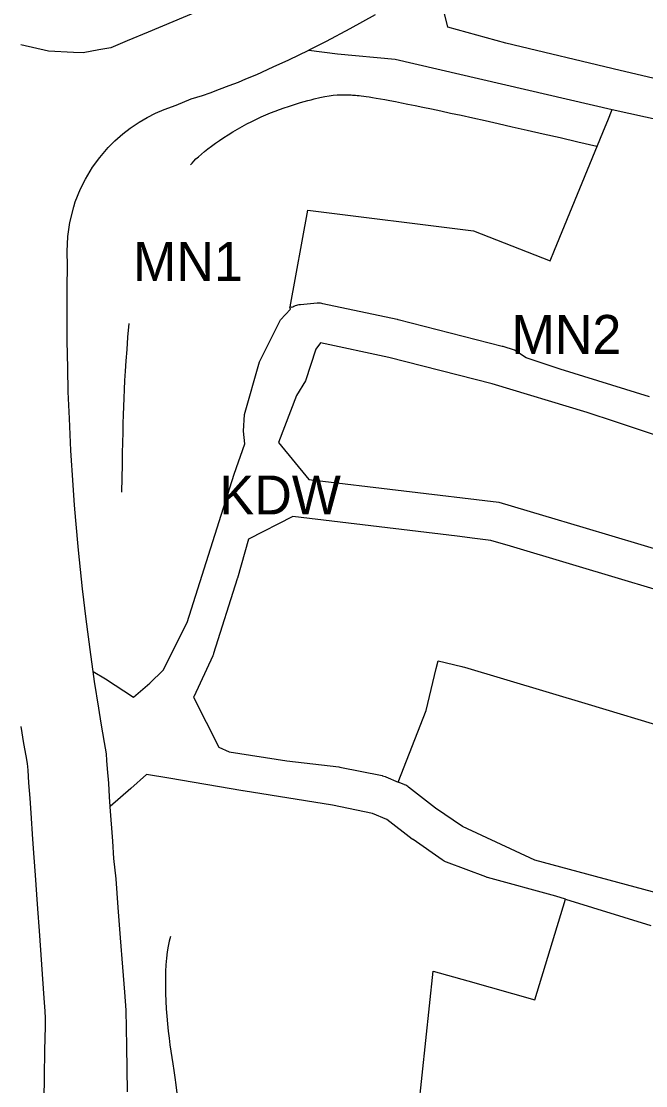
# Model space of a CAD drawing. Extents: x 7413438 to 7416393, y 5541665 to 5544118.
# Drawn here: x 7414642.6 to 7414738.9, y 5542699.5 to 5542863.7 of the extents above; entities that cross this region are included whole.
import ezdxf

# ---------------------------------------------------------------- set-up
doc = ezdxf.new("R2010")
doc.units = 0
for name, color, linetype in [('linie_rozgraniczajace', 7, 'Continuous'), ('linie_zabudowy_nieprzekraczalne', 7, 'Continuous'), ('oznaczenia_przeznaczen', 7, 'Continuous')]:
    doc.layers.add(name, color=color, linetype=linetype)

msp = doc.modelspace()

# ---------------------------------------------------------------- linework, layer by layer
at = {"layer": 'linie_rozgraniczajace'}
for p, q in [((7414708.4, 5542862.85), (7414706.47, 5542870.48)), ((7414669.79, 5542865.24), (7414662.17, 5542862.07)), ((7414697.17, 5542864.75), (7414693.28, 5542862.58)), ((7414662.17, 5542862.07), (7414658.93, 5542860.71)), ((7414693.28, 5542862.58), (7414689.64, 5542860.65)), ((7414717.31, 5542860.37), (7414708.4, 5542862.85)), ((7414646.79, 5542859.15), (7414642.54, 5542860.1)), ((7414658.93, 5542860.71), (7414656.43, 5542859.65)), ((7414689.64, 5542860.65), (7414686.96, 5542859.3)), ((7414734.97, 5542856.15), (7414717.31, 5542860.37)), ((7414650.67, 5542858.95), (7414646.79, 5542859.15)), ((7414652.15, 5542858.88), (7414650.67, 5542858.95)), ((7414654.58, 5542859.32), (7414652.15, 5542858.88)), ((7414656.43, 5542859.65), (7414654.58, 5542859.32)), ((7414683.85, 5542857.8), (7414686.96, 5542859.3)), ((7414686.96, 5542859.3), (7414691.38, 5542858.73)), ((7414691.38, 5542858.73), (7414700.27, 5542857.89)), ((7414681.46, 5542856.7), (7414683.85, 5542857.8)), ((7414700.27, 5542857.89), (7414733.74, 5542850.13)), ((7414677.26, 5542854.85), (7414678.93, 5542855.55)), ((7414678.93, 5542855.55), (7414681.46, 5542856.7)), ((7414746.66, 5542853.39), (7414734.97, 5542856.15)), ((7414673.19, 5542853.28), (7414674.64, 5542853.82)), ((7414674.64, 5542853.82), (7414676.09, 5542854.36)), ((7414676.09, 5542854.36), (7414677.26, 5542854.85)), ((7414668.8, 5542851.76), (7414670.53, 5542852.3)), ((7414670.53, 5542852.3), (7414671.71, 5542852.73)), ((7414671.71, 5542852.73), (7414673.19, 5542853.28)), ((7414664.65, 5542850.11), (7414666.47, 5542850.79)), ((7414666.47, 5542850.79), (7414668.8, 5542851.76)), ((7414660.81, 5542848.2), (7414662.04, 5542848.91)), ((7414662.04, 5542848.91), (7414663.33, 5542849.56)), ((7414663.33, 5542849.56), (7414664.65, 5542850.11)), ((7414733.06, 5542848.45), (7414733.74, 5542850.13)), ((7414733.74, 5542850.13), (7414741.44, 5542848.45)), ((7414658.26, 5542846.38), (7414659.42, 5542847.27)), ((7414659.42, 5542847.27), (7414660.81, 5542848.2)), ((7414724.84, 5542828.41), (7414732.64, 5542847.44)), ((7414732.64, 5542847.44), (7414732.65, 5542847.44)), ((7414732.65, 5542847.44), (7414733.06, 5542848.45)), ((7414733.06, 5542848.45), (7414733.06, 5542848.45)), ((7414656, 5542844.26), (7414657.05, 5542845.31)), ((7414657.05, 5542845.31), (7414658.26, 5542846.38)), ((7414654.7, 5542842.73), (7414656, 5542844.26)), ((7414653.6, 5542841.22), (7414654.7, 5542842.73)), ((7414652.51, 5542839.4), (7414653.6, 5542841.22)), ((7414651.76, 5542837.88), (7414652.51, 5542839.4)), ((7414650.93, 5542835.89), (7414651.76, 5542837.88)), ((7414650.72, 5542835.12), (7414650.93, 5542835.89)), ((7414650.11, 5542832.68), (7414650.72, 5542835.12)), ((7414684.09, 5542819.67), (7414686.78, 5542834.59)), ((7414686.78, 5542834.59), (7414712.33, 5542831.39)), ((7414649.79, 5542830.54), (7414650.11, 5542832.68)), ((7414649.68, 5542828.21), (7414649.79, 5542830.54)), ((7414712.33, 5542831.39), (7414724.16, 5542826.77)), ((7414649.75, 5542826.03), (7414649.68, 5542828.21)), ((7414724.16, 5542826.77), (7414724.84, 5542828.41)), ((7414649.69, 5542822.68), (7414649.75, 5542826.03)), ((7414649.7, 5542820.18), (7414649.69, 5542822.68)), ((7414649.69, 5542814.46), (7414649.7, 5542820.18)), ((7414682.56, 5542817.7), (7414684.14, 5542819.3)), ((7414684, 5542819.59), (7414684.09, 5542819.67)), ((7414684.14, 5542819.3), (7414684, 5542819.59)), ((7414684.39, 5542819.59), (7414684.09, 5542819.67)), ((7414684.49, 5542819.65), (7414684.39, 5542819.59)), ((7414684.66, 5542819.74), (7414684.49, 5542819.65)), ((7414684.84, 5542819.82), (7414684.66, 5542819.74)), ((7414685.03, 5542819.88), (7414684.84, 5542819.82)), ((7414685.22, 5542819.93), (7414685.03, 5542819.88)), ((7414685.41, 5542819.97), (7414685.22, 5542819.93)), ((7414685.6, 5542820), (7414685.41, 5542819.97)), ((7414685.66, 5542820.01), (7414685.6, 5542820)), ((7414688.23, 5542820.23), (7414685.66, 5542820.01)), ((7414688.37, 5542820.24), (7414688.23, 5542820.23)), ((7414688.57, 5542820.24), (7414688.37, 5542820.24)), ((7414688.76, 5542820.23), (7414688.57, 5542820.24)), ((7414688.96, 5542820.2), (7414688.76, 5542820.23)), ((7414689.12, 5542820.17), (7414688.96, 5542820.2)), ((7414700.6, 5542817.73), (7414689.12, 5542820.17)), ((7414679.33, 5542811.19), (7414682.56, 5542817.7)), ((7414700.64, 5542817.72), (7414700.6, 5542817.73)), ((7414700.72, 5542817.7), (7414700.64, 5542817.72)), ((7414716.78, 5542813.58), (7414700.72, 5542817.7)), ((7414649.76, 5542810.23), (7414649.69, 5542814.46)), ((7414688.73, 5542814.12), (7414688.03, 5542813.16)), ((7414699.29, 5542811.87), (7414688.73, 5542814.12)), ((7414688.03, 5542813.16), (7414686.42, 5542808.24)), ((7414716.88, 5542813.56), (7414716.78, 5542813.58)), ((7414716.9, 5542813.55), (7414716.88, 5542813.56)), ((7414718.67, 5542813.02), (7414716.9, 5542813.55)), ((7414720.47, 5542811.8), (7414718.67, 5542813.02)), ((7414677.02, 5542803.09), (7414679.33, 5542811.19)), ((7414715.23, 5542807.79), (7414699.29, 5542811.87)), ((7414725.7, 5542810.06), (7414720.47, 5542811.8)), ((7414649.86, 5542806.59), (7414649.76, 5542810.23)), ((7414739.48, 5542805.82), (7414725.7, 5542810.06)), ((7414686.42, 5542808.24), (7414685.04, 5542805.99)), ((7414729.87, 5542803.39), (7414715.23, 5542807.79)), ((7414650.02, 5542802.45), (7414649.86, 5542806.59)), ((7414685.04, 5542805.99), (7414682.26, 5542798.73)), ((7414676.9, 5542800.49), (7414677.02, 5542803.09)), ((7414734.24, 5542801.94), (7414729.87, 5542803.39)), ((7414650.26, 5542797.49), (7414650.02, 5542802.45)), ((7414738.55, 5542800.51), (7414734.24, 5542801.94)), ((7414677.07, 5542798.52), (7414676.9, 5542800.49)), ((7414763.07, 5542792.25), (7414738.55, 5542800.51)), ((7414675.44, 5542793.84), (7414677.07, 5542798.52)), ((7414682.26, 5542798.73), (7414686.94, 5542793.06)), ((7414650.62, 5542792.14), (7414650.26, 5542797.49)), ((7414668.17, 5542770.96), (7414675.44, 5542793.84)), ((7414686.94, 5542793.06), (7414716.26, 5542789.54)), ((7414650.82, 5542789.08), (7414650.62, 5542792.14)), ((7414716.26, 5542789.54), (7414722.99, 5542787.53)), ((7414651.02, 5542786.69), (7414650.82, 5542789.08)), ((7414651.43, 5542782.12), (7414651.02, 5542786.69)), ((7414684.49, 5542787.31), (7414677.66, 5542783.81)), ((7414709.85, 5542784.27), (7414684.49, 5542787.31)), ((7414722.99, 5542787.53), (7414729.21, 5542785.67)), ((7414729.21, 5542785.67), (7414780.36, 5542770.35)), ((7414677.66, 5542783.81), (7414675.93, 5542777.8)), ((7414712.56, 5542783.95), (7414709.85, 5542784.27)), ((7414715.04, 5542783.65), (7414712.56, 5542783.95)), ((7414718.03, 5542782.75), (7414715.04, 5542783.65)), ((7414652.05, 5542776.16), (7414651.43, 5542782.12)), ((7414718.06, 5542782.74), (7414718.03, 5542782.75)), ((7414735.75, 5542777.44), (7414718.06, 5542782.74)), ((7414675.91, 5542777.73), (7414672.27, 5542766.19)), ((7414675.92, 5542777.78), (7414675.91, 5542777.73)), ((7414675.93, 5542777.8), (7414675.92, 5542777.78)), ((7414758.35, 5542770.68), (7414735.75, 5542777.44)), ((7414652.6, 5542771.51), (7414652.05, 5542776.16)), ((7414653.32, 5542766.01), (7414652.6, 5542771.51)), ((7414664.51, 5542763.63), (7414668.17, 5542770.96)), ((7414653.69, 5542763.4), (7414653.32, 5542766.01)), ((7414672.14, 5542765.84), (7414669.22, 5542759.5)), ((7414672.15, 5542765.88), (7414672.14, 5542765.84)), ((7414672.23, 5542766.06), (7414672.15, 5542765.88)), ((7414672.27, 5542766.19), (7414672.23, 5542766.06)), ((7414706.61, 5542763.85), (7414706.9, 5542765.06)), ((7414706.9, 5542765.06), (7414710.56, 5542764.17)), ((7414653.91, 5542761.86), (7414653.69, 5542763.4)), ((7414653.69, 5542763.4), (7414655.57, 5542762.27)), ((7414662.43, 5542761.61), (7414664.51, 5542763.63)), ((7414705.03, 5542757.37), (7414706.61, 5542763.85)), ((7414710.56, 5542764.17), (7414710.68, 5542764.14)), ((7414710.68, 5542764.14), (7414710.95, 5542764.08)), ((7414710.95, 5542764.08), (7414730.03, 5542758.36)), ((7414654.55, 5542757.76), (7414653.91, 5542761.86)), ((7414655.57, 5542762.27), (7414659.93, 5542759.44)), ((7414659.93, 5542759.44), (7414662.43, 5542761.61)), ((7414669.22, 5542759.5), (7414669.19, 5542759.45)), ((7414669.19, 5542759.45), (7414673.05, 5542751.71)), ((7414730.03, 5542758.36), (7414752.3, 5542751.67)), ((7414654.93, 5542755.44), (7414654.55, 5542757.76)), ((7414700.73, 5542746.35), (7414705.03, 5542757.37)), ((7414642.52, 5542754.94), (7414642.97, 5542752.31)), ((7414655.44, 5542752.46), (7414654.93, 5542755.44)), ((7414642.97, 5542752.31), (7414643.31, 5542750.42)), ((7414655.74, 5542750.7), (7414655.44, 5542752.46)), ((7414673.05, 5542751.71), (7414674.68, 5542751.03)), ((7414643.31, 5542750.42), (7414643.53, 5542749.21)), ((7414655.81, 5542749.69), (7414655.74, 5542750.7)), ((7414674.68, 5542751.03), (7414683.56, 5542749.64)), ((7414643.53, 5542749.21), (7414643.61, 5542748.17)), ((7414655.91, 5542748.39), (7414655.81, 5542749.69)), ((7414656.12, 5542746.2), (7414655.91, 5542748.39)), ((7414683.56, 5542749.64), (7414691.6, 5542748.68)), ((7414691.6, 5542748.68), (7414691.73, 5542748.66)), ((7414691.73, 5542748.66), (7414698.27, 5542747.34)), ((7414643.61, 5542748.17), (7414643.74, 5542746.23)), ((7414661.91, 5542747.52), (7414659.5, 5542745.36)), ((7414665.36, 5542746.96), (7414661.91, 5542747.52)), ((7414676.76, 5542744.98), (7414665.36, 5542746.96)), ((7414698.27, 5542747.34), (7414698.33, 5542747.32)), ((7414698.33, 5542747.32), (7414698.52, 5542747.27)), ((7414698.52, 5542747.27), (7414698.71, 5542747.21)), ((7414698.71, 5542747.21), (7414698.85, 5542747.16)), ((7414698.85, 5542747.16), (7414700.73, 5542746.35)), ((7414643.74, 5542746.23), (7414643.91, 5542743.86)), ((7414656.22, 5542744.05), (7414656.12, 5542746.2)), ((7414659.5, 5542745.36), (7414656.32, 5542742.58)), ((7414701.68, 5542745.95), (7414700.73, 5542746.35)), ((7414701.72, 5542745.93), (7414701.68, 5542745.95)), ((7414701.89, 5542745.85), (7414701.72, 5542745.93)), ((7414702.06, 5542745.75), (7414701.89, 5542745.85)), ((7414702.23, 5542745.64), (7414702.06, 5542745.75)), ((7414702.33, 5542745.56), (7414702.23, 5542745.64)), ((7414706.51, 5542742.34), (7414702.33, 5542745.56)), ((7414643.91, 5542743.86), (7414644.08, 5542741.53)), ((7414656.32, 5542742.58), (7414656.22, 5542744.05)), ((7414676.8, 5542744.98), (7414676.76, 5542744.98)), ((7414690.6, 5542742.77), (7414676.8, 5542744.98)), ((7414656.32, 5542742.55), (7414656.32, 5542742.58)), ((7414656.7, 5542737.22), (7414656.32, 5542742.55)), ((7414696.78, 5542741.52), (7414690.6, 5542742.77)), ((7414710.64, 5542739.47), (7414706.51, 5542742.34)), ((7414644.08, 5542741.53), (7414644.36, 5542737.53)), ((7414698.97, 5542740.58), (7414696.78, 5542741.52)), ((7414702.9, 5542737.54), (7414698.97, 5542740.58)), ((7414721.79, 5542734.27), (7414710.64, 5542739.47)), ((7414644.36, 5542737.53), (7414644.56, 5542734.73)), ((7414656.89, 5542734.53), (7414656.7, 5542737.22)), ((7414703.01, 5542737.47), (7414702.9, 5542737.54)), ((7414703.02, 5542737.46), (7414703.01, 5542737.47)), ((7414707.52, 5542734.33), (7414703.02, 5542737.46)), ((7414644.56, 5542734.73), (7414644.76, 5542731.97)), ((7414657.23, 5542731.41), (7414656.89, 5542734.53)), ((7414707.67, 5542734.23), (7414707.52, 5542734.33)), ((7414707.84, 5542734.13), (7414707.67, 5542734.23)), ((7414708.02, 5542734.05), (7414707.84, 5542734.13)), ((7414708.18, 5542733.98), (7414708.02, 5542734.05)), ((7414714.23, 5542731.71), (7414708.18, 5542733.98)), ((7414746.62, 5542727.59), (7414721.79, 5542734.27)), ((7414644.76, 5542731.97), (7414644.97, 5542728.98)), ((7414657.57, 5542727.01), (7414657.23, 5542731.41)), ((7414714.25, 5542731.7), (7414714.23, 5542731.71)), ((7414714.44, 5542731.64), (7414714.25, 5542731.7)), ((7414714.5, 5542731.63), (7414714.44, 5542731.64)), ((7414725.02, 5542728.76), (7414714.5, 5542731.63)), ((7414644.97, 5542728.98), (7414645.12, 5542726.79)), ((7414726.52, 5542728.29), (7414725.02, 5542728.76)), ((7414657.92, 5542722.29), (7414657.57, 5542727.01)), ((7414721.81, 5542712.75), (7414726.52, 5542728.29)), ((7414726.52, 5542728.29), (7414739.72, 5542724.21)), ((7414645.12, 5542726.79), (7414645.37, 5542723.39)), ((7414645.37, 5542723.39), (7414645.73, 5542718.2)), ((7414658.26, 5542717.8), (7414657.92, 5542722.29)), ((7414645.73, 5542718.2), (7414646.1, 5542713.02)), ((7414658.55, 5542713.92), (7414658.26, 5542717.8)), ((7414703.7, 5542694.5), (7414706.15, 5542717.19)), ((7414706.15, 5542717.19), (7414711.45, 5542715.69)), ((7414711.45, 5542715.69), (7414721.81, 5542712.75)), ((7414658.76, 5542711.15), (7414658.55, 5542713.92)), ((7414646.1, 5542713.02), (7414646.25, 5542710.97)), ((7414646.25, 5542710.97), (7414646.29, 5542709.89)), ((7414658.87, 5542705.58), (7414658.76, 5542711.15)), ((7414646.29, 5542709.89), (7414646.27, 5542708.64)), ((7414646.27, 5542708.64), (7414646.21, 5542704.96)), ((7414646.21, 5542704.96), (7414646.15, 5542700.87)), ((7414658.98, 5542698.53), (7414658.87, 5542705.58)), ((7414646.15, 5542700.87), (7414646.1, 5542697.43))]:
    msp.add_line(p, q, dxfattribs=at)
at = {"layer": 'linie_zabudowy_nieprzekraczalne'}
for points in [[(7414668.72, 5542841.62), (7414669.69, 5542842.89), (7414677.3, 5542848.84), (7414689.33, 5542852.29), (7414692.15, 5542852.6), (7414699.27, 5542851.93), (7414731.39, 5542844.49)], [(7414659.18, 5542817.13), (7414658.2, 5542805.12), (7414658.35, 5542803.67), (7414658.06, 5542791.07)], [(7414665.62, 5542722.5), (7414664.44, 5542719), (7414665.08, 5542703.45), (7414667.5, 5542697.29), (7414667.03, 5542676.29)]]:
    msp.add_open_spline(points, degree=3, dxfattribs=at)

# ---------------------------------------------------------------- texts
at = {"layer": 'oznaczenia_przeznaczen'}
for s, p in [('MN1', (7414659.84, 5542823.68)), ('MN2', (7414718.21, 5542812.43)), ('KDW', (7414673.18, 5542787.65))]:
    msp.add_text(s, height=6, dxfattribs=at).set_placement(p)

doc.saveas('drawing.dxf')
